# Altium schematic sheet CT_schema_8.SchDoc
size 226 x 144 mm
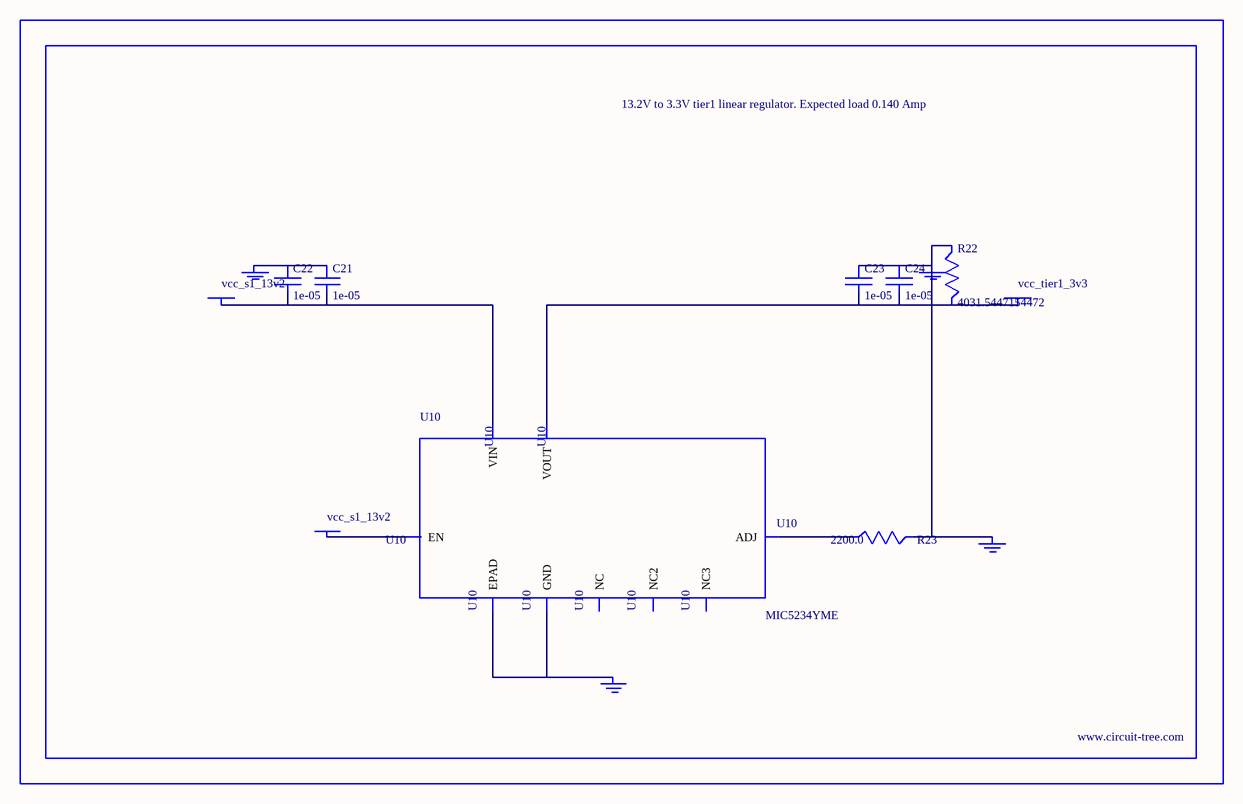
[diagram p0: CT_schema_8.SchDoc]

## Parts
BORDER7  (no value)
C21  1e-05  [C1210]
C22  1e-05  [C1210]
C23  1e-05  [C1210]
C24  1e-05  [C1210]
GND_INSTANCE_7_0  (no value)
GND_INSTANCE_7_1  (no value)
GND_INSTANCE_7_2  (no value)
GND_INSTANCE_7_3  (no value)
POWER_INSTANCE_7_0  vcc_tier1_3v3
POWER_INSTANCE_7_1  vcc_s1_13v2
POWER_INSTANCE_7_2  vcc_s1_13v2
R22  4031.5447154472  [R0603]
R23  2200.0  [R0603]
U10  MIC5234YME  [SOIC-8_EP]

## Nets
NetC21_1: C21.1 C22.1 GND_INSTANCE_7_3.0(GND)
NetC21_2: C21.2 C22.2 POWER_INSTANCE_7_2.0(PWR) U10.8(VIN)
NetC23_1: C23.1 C24.1 GND_INSTANCE_7_0.0(GND) GND_INSTANCE_7_1.0(GND) R22.1 R23.2
NetC23_2: C23.2 C24.2 POWER_INSTANCE_7_0.0(PWR) R22.2 U10.1(VOUT)
NetGND_INSTANCE_7_2_0: GND_INSTANCE_7_2.0(GND) U10.7(GND) U10.EPAD
NetPOWER_INSTANCE_7_1_0: POWER_INSTANCE_7_1.0(PWR) U10.5(EN)
NetR23_1: R23.1 U10.4(ADJ)

Not connected (* = marked no-connect by the designer): U10 2(NC) 3(NC2) 6(NC3)

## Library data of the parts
BORDER7 = BORDER_PAGE7
C21-C24 = C1210C106K5PACTU
GND_INSTANCE_7_0-GND_INSTANCE_7_3 = GND
POWER_INSTANCE_7_0-POWER_INSTANCE_7_2 = PWR
R22 = R22
R23 = RC0603JR-072K2L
